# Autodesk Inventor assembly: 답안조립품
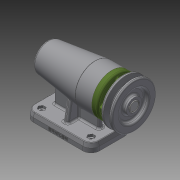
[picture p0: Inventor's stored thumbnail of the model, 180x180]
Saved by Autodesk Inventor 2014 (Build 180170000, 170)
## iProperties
Created: 2017-01
Part Number: 답안조립품
Document SubType Name: Assembly
Designer: USER
Author: USER
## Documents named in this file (12)
- C:\Users\USER\Desktop\470107V1010\답안조립품.iam
- C:\Users\USER\Desktop\470107V1010\V벨트풀리.ipt
- C:\Users\USER\Desktop\470107V1010\멈춤나사 M3x8.ipt
- C:\Users\USER\Desktop\470107V1010\베어링 6004.ipt
- C:\Users\USER\Desktop\470107V1010\베어링 51202.ipt
- C:\Users\USER\Desktop\470107V1010\본체.ipt
- C:\Users\USER\Desktop\470107V1010\볼트 M4 x 12.ipt
- C:\Users\USER\Desktop\470107V1010\어댑터슬리브.ipt
- C:\Users\USER\Desktop\470107V1010\오일 실.ipt
- C:\Users\USER\Desktop\470107V1010\축.ipt
- C:\Users\USER\Desktop\470107V1010\커버.ipt
- C:\Users\USER\Desktop\470107V1010\키 5 x 5 x 16.ipt
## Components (2 placed, 2 different names)
1. V벨트풀리:1
2. ISO 4762 M4 x 12:1
